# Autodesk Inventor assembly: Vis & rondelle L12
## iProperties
Author: Flavien MARTY
Shininess: 21.0
PropertySet Name: _Private Model Information
Created: 2001-10
Part Number: Vis & rondelle L12
Document SubType Name: Assemblage
Designer: Flavien MARTY
Control State: 0
Master: False
Checked Out: False
PropertySet Name: Design Tracking Control
Density: 0.0
Volumn: 0.0
Area: 0.0
PropertySet Name: Model Information
